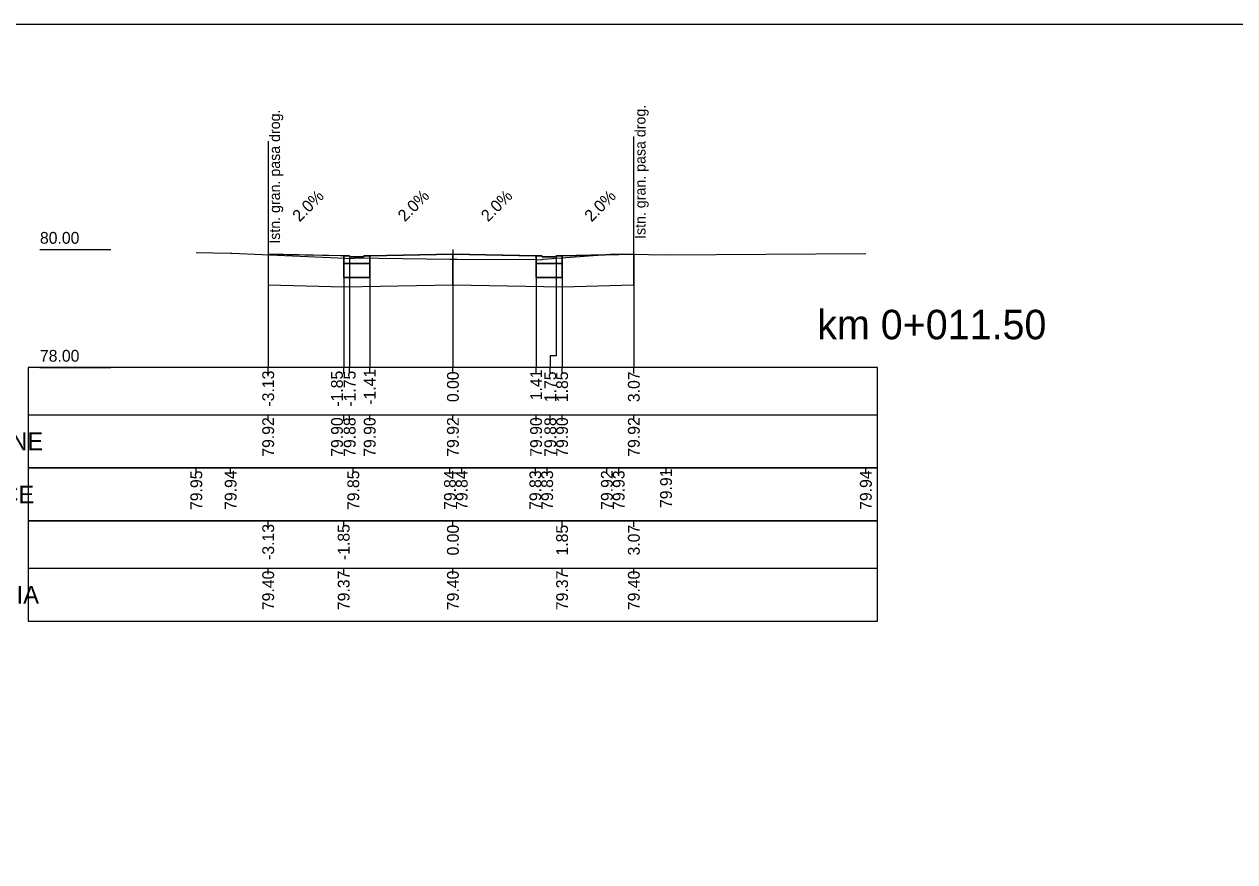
# Model space of a CAD drawing. Extents: x 7492871 to 7493499, y 5802964 to 5802992.
# Drawn here: x 7492882.66 to 7492903.18, y 5802978.08 to 5802992.28 of the extents above; entities that cross this region are included whole.
import ezdxf

# ---------------------------------------------------------------- set-up
doc = ezdxf.new("R2010")
doc.units = 0
for name, color, linetype in [('_wydruk', 7, 'Continuous'), ('opisy_ramki_pop', 7, 'Continuous'), ('pop_comp_kostka', 7, 'Continuous'), ('pop_comp_lawa', 7, 'Continuous'), ('pop_comp_scieralna', 7, 'Continuous'), ('pop_granica_istn', 7, 'Continuous'), ('pop_opis', 7, 'Continuous'), ('pop_os', 7, 'Continuous'), ('pop_pikietaz', 7, 'Continuous'), ('pop_teren', 7, 'Continuous')]:
    doc.layers.add(name, color=color, linetype=linetype)

msp = doc.modelspace()

# ---------------------------------------------------------------- linework, layer by layer
msp.add_lwpolyline([(7492886.794, 5802988.381), (7492886.808, 5802988.381), (7492888.016, 5802988.357), (7492888.074, 5802988.356), (7492888.173, 5802988.356), (7492888.174, 5802988.356), (7492888.175, 5802988.336), (7492888.411, 5802988.336), (7492888.414, 5802988.336), (7492888.415, 5802988.356), (7492888.416, 5802988.356), (7492888.515, 5802988.356), (7492888.53, 5802988.356), (7492889.925, 5802988.384), (7492891.319, 5802988.356), (7492891.335, 5802988.356), (7492891.434, 5802988.356), (7492891.435, 5802988.356), (7492891.436, 5802988.336), (7492891.672, 5802988.336), (7492891.675, 5802988.336), (7492891.676, 5802988.356), (7492891.775, 5802988.356), (7492891.776, 5802988.356), (7492892.979, 5802988.38), (7492892.992, 5802988.38)])
at = {"layer": '_wydruk'}
msp.add_lwpolyline([(7492871.369, 5802992.281), (7493499.283, 5802992.281), (7493499.283, 5802963.881), (7492871.369, 5802963.881)], close=True, dxfattribs=at)
at = {"layer": 'opisy_ramki_pop'}
for points in [[(7492886.794, 5802987.861), (7492886.794, 5802986.659), (7492886.794, 5802986.659), (7492886.794, 5802986.459)], [(7492888.074, 5802987.827), (7492888.074, 5802986.659), (7492888.074, 5802986.659), (7492888.074, 5802986.459)], [(7492889.925, 5802987.864), (7492889.925, 5802986.659), (7492889.925, 5802986.659), (7492889.925, 5802986.459)], [(7492891.776, 5802987.827), (7492891.776, 5802986.659), (7492891.776, 5802986.659), (7492891.776, 5802986.459)], [(7492892.992, 5802987.86), (7492892.992, 5802986.659), (7492892.992, 5802986.659), (7492892.992, 5802986.459)]]:
    msp.add_lwpolyline(points, dxfattribs=at)
at = {"layer": 'pop_comp_kostka'}
for p, q in [((7492888.174, 5802988.356), (7492888.074, 5802988.356)), ((7492888.074, 5802988.356), (7492888.074, 5802988.226)), ((7492888.074, 5802988.226), (7492888.515, 5802988.226)), ((7492888.175, 5802988.336), (7492888.174, 5802988.356)), ((7492888.414, 5802988.336), (7492888.175, 5802988.336)), ((7492888.415, 5802988.356), (7492888.414, 5802988.336)), ((7492888.515, 5802988.356), (7492888.415, 5802988.356)), ((7492888.515, 5802988.226), (7492888.515, 5802988.356)), ((7492891.435, 5802988.356), (7492891.335, 5802988.356)), ((7492891.335, 5802988.356), (7492891.335, 5802988.226)), ((7492891.335, 5802988.226), (7492891.776, 5802988.226)), ((7492891.436, 5802988.336), (7492891.435, 5802988.356)), ((7492891.675, 5802988.336), (7492891.436, 5802988.336)), ((7492891.676, 5802988.356), (7492891.675, 5802988.336)), ((7492891.776, 5802988.356), (7492891.676, 5802988.356)), ((7492891.776, 5802988.226), (7492891.776, 5802988.356))]:
    msp.add_line(p, q, dxfattribs=at)
at = {"layer": 'pop_comp_lawa'}
for p, q in [((7492888.515, 5802988.226), (7492888.074, 5802988.226)), ((7492888.074, 5802988.226), (7492888.074, 5802987.985)), ((7492888.515, 5802987.985), (7492888.515, 5802988.226)), ((7492891.776, 5802988.226), (7492891.335, 5802988.226)), ((7492891.335, 5802988.226), (7492891.335, 5802987.985)), ((7492891.776, 5802987.985), (7492891.776, 5802988.226)), ((7492888.074, 5802987.985), (7492888.515, 5802987.985)), ((7492891.335, 5802987.985), (7492891.776, 5802987.985))]:
    msp.add_line(p, q, dxfattribs=at)
at = {"layer": 'pop_comp_scieralna'}
for p, q in [((7492888.074, 5802988.356), (7492886.794, 5802988.381)), ((7492886.794, 5802988.381), (7492886.794, 5802987.861)), ((7492889.925, 5802988.384), (7492888.515, 5802988.356)), ((7492889.925, 5802987.864), (7492889.925, 5802988.384)), ((7492891.335, 5802988.356), (7492889.925, 5802988.384)), ((7492889.925, 5802988.384), (7492889.925, 5802987.864)), ((7492892.992, 5802988.38), (7492891.776, 5802988.356)), ((7492892.992, 5802987.86), (7492892.992, 5802988.38)), ((7492888.074, 5802987.985), (7492888.074, 5802988.356)), ((7492888.515, 5802988.356), (7492888.515, 5802987.985)), ((7492891.335, 5802987.985), (7492891.335, 5802988.356)), ((7492891.776, 5802988.356), (7492891.776, 5802987.985)), ((7492888.515, 5802987.985), (7492888.074, 5802987.985)), ((7492891.776, 5802987.985), (7492891.335, 5802987.985)), ((7492886.794, 5802987.861), (7492888.074, 5802987.827)), ((7492888.074, 5802987.827), (7492889.925, 5802987.864)), ((7492889.925, 5802987.864), (7492891.776, 5802987.827)), ((7492891.776, 5802987.827), (7492892.992, 5802987.86))]:
    msp.add_line(p, q, dxfattribs=at)
at = {"layer": 'pop_granica_istn'}
for p, q in [((7492886.797, 5802988.798), (7492886.797, 5802990.298)), ((7492892.992, 5802988.879), (7492892.992, 5802990.379)), ((7492886.797, 5802988.298), (7492886.797, 5802988.798)), ((7492892.992, 5802988.379), (7492892.992, 5802988.879))]:
    msp.add_line(p, q, dxfattribs=at)
at = {"layer": 'pop_opis'}
for p, q in [((7492882.925, 5802988.459), (7492884.125, 5802988.459)), ((7492882.725, 5802986.459), (7492882.725, 5802984.759)), ((7492882.725, 5802986.459), (7492882.725, 5802984.759)), ((7492882.725, 5802986.459), (7492882.725, 5802984.759)), ((7492882.725, 5802986.459), (7492882.725, 5802984.759)), ((7492882.925, 5802986.459), (7492884.125, 5802986.459)), ((7492886.794, 5802986.359), (7492886.794, 5802986.459)), ((7492888.074, 5802986.359), (7492888.074, 5802986.459)), ((7492888.175, 5802986.359), (7492888.175, 5802986.459)), ((7492888.515, 5802986.359), (7492888.515, 5802986.459)), ((7492889.925, 5802986.359), (7492889.925, 5802986.459)), ((7492891.335, 5802986.359), (7492891.335, 5802986.459)), ((7492891.576, 5802986.359), (7492891.576, 5802986.459)), ((7492891.776, 5802986.359), (7492891.776, 5802986.459)), ((7492892.992, 5802986.359), (7492892.992, 5802986.459)), ((7492882.725, 5802985.659), (7492897.125, 5802985.659)), ((7492882.725, 5802985.659), (7492897.125, 5802985.659)), ((7492882.725, 5802985.659), (7492897.125, 5802985.659)), ((7492882.725, 5802985.659), (7492897.125, 5802985.659)), ((7492886.794, 5802985.559), (7492886.794, 5802985.659)), ((7492888.074, 5802985.559), (7492888.074, 5802985.659)), ((7492888.175, 5802985.559), (7492888.175, 5802985.659)), ((7492888.515, 5802985.559), (7492888.515, 5802985.659)), ((7492889.925, 5802985.559), (7492889.925, 5802985.659)), ((7492891.335, 5802985.559), (7492891.335, 5802985.659)), ((7492891.576, 5802985.559), (7492891.576, 5802985.659)), ((7492891.776, 5802985.559), (7492891.776, 5802985.659)), ((7492892.992, 5802985.559), (7492892.992, 5802985.659)), ((7492882.725, 5802984.759), (7492882.725, 5802983.859)), ((7492885.576, 5802984.659), (7492885.576, 5802984.759)), ((7492886.158, 5802984.659), (7492886.158, 5802984.759)), ((7492888.237, 5802984.659), (7492888.237, 5802984.759)), ((7492889.875, 5802984.659), (7492889.875, 5802984.759)), ((7492890.075, 5802984.659), (7492890.075, 5802984.759)), ((7492891.323, 5802984.659), (7492891.323, 5802984.759)), ((7492891.523, 5802984.659), (7492891.523, 5802984.759)), ((7492892.535, 5802984.659), (7492892.535, 5802984.759)), ((7492892.735, 5802984.659), (7492892.735, 5802984.759)), ((7492893.538, 5802984.659), (7492893.538, 5802984.759)), ((7492896.925, 5802984.659), (7492896.925, 5802984.759)), ((7492882.725, 5802983.859), (7492882.725, 5802982.159)), ((7492886.794, 5802983.759), (7492886.794, 5802983.859)), ((7492888.074, 5802983.759), (7492888.074, 5802983.859)), ((7492889.925, 5802983.759), (7492889.925, 5802983.859)), ((7492891.776, 5802983.759), (7492891.776, 5802983.859)), ((7492892.992, 5802983.759), (7492892.992, 5802983.859)), ((7492882.725, 5802983.059), (7492897.125, 5802983.059)), ((7492886.794, 5802982.959), (7492886.794, 5802983.059)), ((7492888.074, 5802982.959), (7492888.074, 5802983.059)), ((7492889.925, 5802982.959), (7492889.925, 5802983.059)), ((7492891.776, 5802982.959), (7492891.776, 5802983.059)), ((7492892.992, 5802982.959), (7492892.992, 5802983.059))]:
    msp.add_line(p, q, dxfattribs=at)
for points in [[(7492886.794, 5802988.381), (7492886.794, 5802986.659), (7492886.794, 5802986.659), (7492886.794, 5802986.459)], [(7492889.925, 5802988.384), (7492889.925, 5802986.659), (7492889.925, 5802986.659), (7492889.925, 5802986.459)], [(7492892.992, 5802988.38), (7492892.992, 5802986.659), (7492892.992, 5802986.659), (7492892.992, 5802986.459)], [(7492888.074, 5802988.356), (7492888.074, 5802986.659), (7492888.074, 5802986.659), (7492888.074, 5802986.459)], [(7492888.175, 5802988.336), (7492888.175, 5802986.659), (7492888.175, 5802986.659), (7492888.175, 5802986.459)], [(7492888.515, 5802988.356), (7492888.515, 5802986.659), (7492888.515, 5802986.659), (7492888.515, 5802986.459)], [(7492891.335, 5802988.356), (7492891.335, 5802986.659), (7492891.335, 5802986.659), (7492891.335, 5802986.459)], [(7492891.675, 5802988.336), (7492891.675, 5802986.659), (7492891.576, 5802986.659), (7492891.576, 5802986.459)], [(7492891.776, 5802988.356), (7492891.776, 5802986.659), (7492891.776, 5802986.659), (7492891.776, 5802986.459)]]:
    msp.add_lwpolyline(points, dxfattribs=at)
for points in [[(7492882.725, 5802986.459), (7492882.725, 5802984.759), (7492897.125, 5802984.759), (7492897.125, 5802986.459)], [(7492882.725, 5802986.459), (7492882.725, 5802984.759), (7492897.125, 5802984.759), (7492897.125, 5802986.459)], [(7492882.725, 5802986.459), (7492882.725, 5802984.759), (7492897.125, 5802984.759), (7492897.125, 5802986.459)], [(7492882.725, 5802986.459), (7492882.725, 5802984.759), (7492897.125, 5802984.759), (7492897.125, 5802986.459)], [(7492882.725, 5802984.759), (7492882.725, 5802983.859), (7492897.125, 5802983.859), (7492897.125, 5802984.759)], [(7492882.725, 5802983.859), (7492882.725, 5802982.159), (7492897.125, 5802982.159), (7492897.125, 5802983.859)]]:
    msp.add_lwpolyline(points, close=True, dxfattribs=at)
at = {"layer": 'pop_os'}
msp.add_line((7492889.925, 5802988.459), (7492889.925, 5802986.459), dxfattribs=at)
at = {"layer": 'pop_teren'}
msp.add_lwpolyline([(7492885.576, 5802988.412), (7492886.158, 5802988.401), (7492886.176, 5802988.398), (7492888.237, 5802988.309), (7492888.266, 5802988.319), (7492889.875, 5802988.299), (7492889.996, 5802988.297), (7492891.323, 5802988.29), (7492891.428, 5802988.288), (7492891.454, 5802988.296), (7492892.535, 5802988.376), (7492892.642, 5802988.386), (7492893.538, 5802988.373), (7492896.925, 5802988.396)], dxfattribs=at)

# ---------------------------------------------------------------- texts
at = {"layer": 'pop_granica_istn'}
for p in [(7492893.19, 5802988.64), (7492886.995, 5802988.559)]:
    msp.add_text('Istn. gran. pasa drog.', height=0.18, rotation=90, dxfattribs=at).set_placement(p)
at = {"layer": 'pop_opis'}
for s, rotation, p in [('2.0%', 45, (7492887.325, 5802988.918)), ('2.0%', 45, (7492889.111, 5802988.92)), ('2.0%', 45, (7492890.521, 5802988.92)), ('2.0%', 45, (7492892.275, 5802988.918)), ('-3.13', 90, (7492886.894, 5802985.798)), ('-1.85', 90, (7492888.06, 5802985.796)), ('-1.75', 90, (7492888.275, 5802985.796)), ('-1.41', 90, (7492888.615, 5802985.829)), ('0.00', 90, (7492890.025, 5802985.874)), ('1.41', 90, (7492891.435, 5802985.905)), ('1.75', 90, (7492891.676, 5802985.873)), ('1.85', 90, (7492891.876, 5802985.873)), ('3.07', 90, (7492893.092, 5802985.874)), ('79.92', 90, (7492886.894, 5802984.948)), ('79.90', 90, (7492888.06, 5802984.947)), ('79.88', 90, (7492888.275, 5802984.946)), ('79.90', 90, (7492888.615, 5802984.947)), ('79.92', 90, (7492890.025, 5802984.948)), ('79.90', 90, (7492891.435, 5802984.947)), ('79.88', 90, (7492891.676, 5802984.946)), ('79.90', 90, (7492891.876, 5802984.947)), ('79.92', 90, (7492893.092, 5802984.948)), ('79.95', 90, (7492885.676, 5802984.045)), ('79.94', 90, (7492886.258, 5802984.047)), ('79.85', 90, (7492888.337, 5802984.045)), ('79.84', 90, (7492889.975, 5802984.047)), ('79.84', 90, (7492890.175, 5802984.047)), ('79.83', 90, (7492891.423, 5802984.047)), ('79.83', 90, (7492891.623, 5802984.047)), ('79.92', 90, (7492892.635, 5802984.048)), ('79.93', 90, (7492892.835, 5802984.047)), ('79.91', 90, (7492893.638, 5802984.078)), ('79.94', 90, (7492897.025, 5802984.047)), ('-3.13', 90, (7492886.894, 5802983.198)), ('-1.85', 90, (7492888.174, 5802983.196)), ('0.00', 90, (7492890.025, 5802983.274)), ('1.85', 90, (7492891.876, 5802983.273)), ('3.07', 90, (7492893.092, 5802983.274)), ('79.40', 90, (7492886.894, 5802982.347)), ('79.37', 90, (7492888.174, 5802982.347)), ('79.40', 90, (7492890.025, 5802982.347)), ('79.37', 90, (7492891.876, 5802982.347)), ('79.40', 90, (7492893.092, 5802982.347))]:
    msp.add_text(s, height=0.2, rotation=rotation, dxfattribs=at).set_placement(p)
for s, height, p in [('80.00', 0.2, (7492882.925, 5802988.559)), ('78.00', 0.2, (7492882.925, 5802986.559)), ('RZĘDNE PROJEKTOWANE', 0.3, (7492877.853, 5802985.059)), ('RZĘDNE PROJEKTOWANE', 0.3, (7492877.853, 5802985.059)), ('RZĘDNE PROJEKTOWANE', 0.3, (7492877.853, 5802985.059)), ('RZĘDNE PROJEKTOWANE', 0.3, (7492877.853, 5802985.059)), ('RZĘDNE ISTNIEJĄCE', 0.3, (7492878.749, 5802984.159)), ('RZĘDNE KORYTOWANIA', 0.3, (7492878.139, 5802982.459))]:
    msp.add_text(s, height=height, dxfattribs=at).set_placement(p)
at = {"layer": 'pop_pikietaz'}
msp.add_text('km 0+011.50', height=0.5, dxfattribs=at).set_placement((7492896.101, 5802986.939))

doc.saveas('drawing.dxf')
